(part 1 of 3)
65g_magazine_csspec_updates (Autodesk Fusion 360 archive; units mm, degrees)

design "65g_magazine_csspec_updates" references "65_g_floorplate"
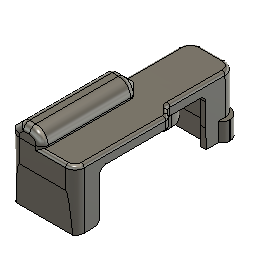
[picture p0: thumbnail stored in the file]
parameter "CartrigeOAL" = 57.9
parameter "magazineShoulder" = 35.6
parameter "feedLipRadius" = 5.6
parameter "primaryWallThickness" = 2
parameter "feedliplength" = 29.6
parameter "frontWidth" = 16
parameter "rearwidth" = 22
parameter "addtlfeedlipthickness" = 3.5
parameter "bananaFactor" = 1509
parameter "floorplateclearance" = 2
parameter "followerOffset" = -0.75
parameter "d1137" = 350
parameter "d372" = 1
parameter "d374" = 0.7
parameter "d376" = 0.7
parameter "d377" = -1
parameter "d378" = 0
parameter "d380" = 0.5
parameter "d387" = 7
parameter "d389" = 1
parameter "d390" = 4
parameter "d391" = 0.75
parameter "d392" = -9
parameter "d393" = 0
parameter "d394" = 10
parameter "d400" = 10
parameter "d401" = 5
parameter "d402" = -0.5
parameter "d403" = 0
parameter "d404" = 0
parameter "d405" = 0
parameter "d406" = 4
parameter "d407" = 3
parameter "d412" = 17
parameter "d413" = 1.5
parameter "d415" = 3
parameter "d418" = 6
parameter "d419" = 1.5
base_feature "Base Feature1" bodies "follower", "mag body", "feed geometry", "random cube", "placeholder to establish center"
derived_base_feature "Derived Base Feature2" bodies "main body", "updated lock lug", "template lock lug from m76"
remove_body "RemoveBody1"
sketch "top down profile" plane through (0, 0, 0) normal (0, 1, 0) x axis (1, 0, 0)
  line L1 (-11, 0) -> (0, 0)
  line L2 (0, 57.9) -> (0, 0)
  line L3 (-11, 35.6) -> (-11, 0)
  line L4 (-8, 44.9274) -> (-8, 53.9)
  line L5 (-4, 57.9) -> (0, 57.9)
  line L6 (-4, 57.9) -> (0, 57.9)
  line L7 (0, 57.9) -> (0, 0)
  line L8 (11, 35.6) -> (11, 0)
  line L9 (8, 44.9274) -> (8, 53.9)
  line L10 (4, 57.9) -> (0, 57.9)
  line L11 (11, 0) -> (0, 0)
  line L12 (-13, -2) -> (0, -2)
  line L13 (-4.2574, 61.8) -> (0, 61.8)
  line L14 (-13, 37) -> (-13, -2)
  line L15 (-6.3787, 60.9213) -> (-10.1219, 57.1781)
  line L16 (6.3787, 60.9213) -> (10.1219, 57.1781)
  line L17 (13, 37) -> (13, -2)
  line L18 (13, -2) -> (0, -2)
  line L19 (4.2574, 61.8) -> (0, 61.8)
  line L20 (-11, 27.6) -> (-13, 27.6)
  line L21 (-11, -2) -> (-11, 0)
  line L22 (-9.4578, 32.9452) -> (-8.5625, 43.1785)
  line L23 (0.2269, 43.1785) -> (-8.5625, 43.1785)
  line L24 (-9.9889, 31.486) -> (-11, 30.042)
  line L25 (-11.7322, 43.1785) -> (-8.5625, 43.1785)
  line L26 (-11, 49.3) -> (-8, 49.3)
  line L27 (-30.8129, 55.0827) -> (-11, 55)
  line L28 (-30.9385, 25) -> (-30.8129, 55.0827)
  line L29 (-13, 25) -> (-30.9385, 25)
  line L30 (-11, 45.4853) -> (-11, 55)
  line L31 (11, 45.4853) -> (11, 55)
  line L32 (-6, -4) -> (6, -4)
  line L33 (6, -2) -> (6, -4)
  line L34 (-6, -2) -> (-6, -4)
  arc A1 centre (-4, 53.9) radius 4 clockwise from (-8, 53.9) to (-4, 57.9)
  arc A2 centre (2, 35.6) radius 13 clockwise from (-11, 35.6) to (-8.5625, 43.1785)
  arc A3 centre (-11, 44.9274) radius 3 clockwise from (-8, 44.9274) to (-8.5625, 43.1785)
  arc A4 centre (-2, 35.6) radius 13 clockwise from (8.5625, 43.1785) to (11, 35.6)
  arc A5 centre (11, 44.9274) radius 3 clockwise from (8.5625, 43.1785) to (8, 44.9274)
  arc A6 centre (4, 53.9) radius 4 clockwise from (4, 57.9) to (8, 53.9)
  arc A7 centre (2, 37) radius 15 clockwise from (-13, 37) to (-11.4211, 43.6989)
  arc A8 centre (-15, 45.4853) radius 4 clockwise from (-11, 45.4853) to (-11.4211, 43.6989)
  arc A9 centre (-8.0005, 55.0568) radius 3 clockwise from (-11, 55) to (-10.1219, 57.1781)
  arc A10 centre (-4.2574, 58.8) radius 3 clockwise from (-6.3787, 60.9213) to (-4.2574, 61.8)
  arc A11 centre (4.2574, 58.8) radius 3 clockwise from (4.2574, 61.8) to (6.3787, 60.9213)
  arc A12 centre (8.0005, 55.0568) radius 3 clockwise from (10.1219, 57.1781) to (11, 55)
  arc A13 centre (15, 45.4853) radius 4 clockwise from (11.4211, 43.6989) to (11, 45.4853)
  arc A14 centre (-2, 37) radius 15 clockwise from (11.4211, 43.6989) to (13, 37)
  arc A15 centre (-12.4464, 33.2067) radius 3 clockwise from (-9.4578, 32.9452) to (-9.9889, 31.486)
  circle C1 centre (-10.808, 41.9164) radius 1.2808
  point P1 (0, 0)
  point P2 (0, 0)
  point P4 (0, 0)
  point P25 (0, 0)
  point P3 (-11, 0)
  point P16 (11, 0)
  point P14 (0, 0)
  point P5 (0, 57.9)
  point P15 (0, 57.9)
  point P7 (-4, 57.9)
  point P24 (4, 57.9)
  point P8 (-8, 53.9)
  point P22 (8, 53.9)
  point P10 (-11, 35.6)
  point P17 (11, 35.6)
  point P12 (-8, 44.9274)
  point P21 (8, 44.9274)
  point P13 (-8.5625, 43.1785)
  point P19 (8.5625, 43.1785)
  point P33 (-5.5, 61.8)
  point P26 (0, -2)
  point P52 (0, -2)
  point P27 (-13, -2)
  point P51 (13, -2)
  point P28 (-13, 37)
  point P50 (13, 37)
  point P30 (-11, 45.4853)
  point P46 (11, 45.4853)
  point P31 (-11.4211, 43.6989)
  point P48 (11.4211, 43.6989)
  point P34 (-10.1219, 57.1781)
  point P43 (10.1219, 57.1781)
  point P35 (-11, 55)
  point P45 (11, 55)
  point P37 (-6.3787, 60.9213)
  point P42 (6.3787, 60.9213)
  point P38 (-4.2574, 61.8)
  point P41 (4.2574, 61.8)
  point P54 (-13, 27.6)
  point P55 (-11, 27.6)
  point P56 (-11, -2)
  point P58 (-11, 30.042)
  point P62 (-11.7322, 43.1785)
  point P63 (-8, 49.3)
  point P67 (-13, 25)
  point P70 (6, -2)
  point P71 (-6, -2)
  point P68 (6, -4)
  point P69 (-6, -4)
  point P72 (-10.808, 41.9164)
  coincident P1 P2
  horizontal L1
  coincident P1 P4
  perpendicular L1 L2
  perpendicular L1 L3
  perpendicular L1 L4
  perpendicular L2 L5
  tangent L5 A1
  tangent L4 A1
  tangent L6 A1
  tangent L3 A2
  tangent A2 A3
  tangent L4 A3
  symmetric P2 L2 P25
  symmetric P3 L2 P16
  symmetric P4 L2 P14
  symmetric P5 L2 P15
  symmetric L2 P7 P24
  symmetric L2 A1 A6
  symmetric L2 P8 P22
  symmetric L2 P10 P17
  symmetric L2 A2 A4
  symmetric L2 P12 P21
  symmetric L2 P13 P19
  symmetric L2 A3 A5
  horizontal L12
  horizontal L13
  perpendicular L12 L14
  tangent L14 A7
  tangent A7 A8
  tangent L15 A9
  coincident P33 L15
  coincident L13 P33
  tangent L15 A10
  tangent L13 A10
  equal A9 A10
  symmetric L2 P26 P52
  symmetric L2 P27 P51
  symmetric L2 P28 P50
  symmetric L2 A7 A14
  symmetric L2 P30 P46
  symmetric L2 P31 P48
  symmetric L2 A8 A13
  symmetric L2 P34 P43
  symmetric L2 P35 P45
  symmetric L2 A9 A12
  symmetric L2 P37 P42
  symmetric L2 P38 P41
  symmetric L2 A10 A11
  coincident L14 P54
  coincident L3 P55
  perpendicular L3 L20
  coincident L12 P56
  perpendicular L12 L21
  horizontal L23
  coincident L3 P58
  tangent L22 A15
  tangent L24 A15
  horizontal L25
  coincident A8 P62
  coincident L4 P63
  perpendicular L27 L28
  coincident L14 P67
  perpendicular L14 L29
  tangent A8 L30
  vertical L30
  parallel L11 L32
  coincident L18 P70
  perpendicular L18 L33
  coincident L12 P71
  perpendicular L12 L34
  tangent A2 C1
  tangent A7 C1
  dimension "d571" distance P2 P3 = 11 (= "rearwidth / 2")
  dimension "d572" distance P4 P5 = 57.9 (= "CartrigeOAL")
  dimension "d573" distance P5 L4 = 8 (= "frontWidth / 2")
  dimension "d574" diameter A1 = 8
  dimension "d577" diameter A3 = 6
  dimension "d578" distance P26 P27 = 13 (= "d571 + 2 mm")
  dimension "d579" distance L1 L12 = 2 (= "primaryWallThickness")
  dimension "d580" distance L12 L13 = 63.8 (= "d572 + 5.9 mm")
  dimension "d586" radius A8 = 4
  dimension "d590" radius A9 = 3
  dimension "d591" angle L13 L15 = 135
  dimension "d601" distance L12 L20 = 29.6 (= "feedliplength")
  dimension "d618" angle L22 L23 = 95
  dimension "d622" radius A15 = 3
  dimension "d623" angle L3 L24 = 145
  dimension "d679" distance L13 L26 = 12.5
  dimension "d681" distance L13 P35 = 6.8
  dimension "d683" distance L3 L14 = 2 (= "d579")
  dimension "d685" distance P3 P10 = 35.6 (= "magazineShoulder")
  dimension "d686" distance L1 P28 = 37 (= "d685 + 1.4 mm")
  dimension "d699" distance P58 L25 = 13.1365
  dimension "d700" distance L7 L30 = 11 (= "d573 + 3 mm")
  dimension "d754" distance P68 P69 = 12
  dimension "d755" distance L7 P68 = 6 (= "d754 / 2")
  dimension "d756" distance L18 L32 = 2
  dimension "d779" diameter C1 = 2.5616
  dimension "d780" distance P30 P72 = 3.5688
sketch "Sketch4" plane through (0, 0, 0) normal (0, 1, 0) x axis (1, 0, 0)
  line L1 (2.35, 53.733) -> (2.35, 46.32)
  line L2 (2.35, 53.733) -> (2.35, 52.4025)
  line L3 (2.35, 48.3729) -> (2.35, 52.4025)
  line L4 (2.35, 45) -> (2.35, 48.3729)
  line L5 (2.35, 46.32) -> (2.35, 45)
  curve K1 (1.7875, 44.5687) -> (-0.65, 36.9798)
  line L6 (1.7875, 44.5687) -> (1.7875, 43.2511)
  line L7 (-0.65, 36.9798) -> (-0.65, 35.6726)
  line L8 (-0.65, 36.9798) -> (-0.65, 1.2627)
  line L9 (-0.65, 36.9798) -> (-0.65, 35.6726)
  line L10 (-0.65, 29.2298) -> (-0.65, 35.6726)
  line L11 (-0.65, 0.0025) -> (-0.65, 29.2298)
  line L12 (-0.65, 0.0025) -> (-0.65, 1.2627)
  curve K2 (2.35, 46.32) -> (1.7875, 44.5687)
  line L13 (2.35, 46.32) -> (2.35, 45)
  line L14 (1.7875, 44.5687) -> (1.7875, 43.2511)
  line L15 (0.8031, 31.5304) -> (1.7875, 43.2511)
  line L16 (-0.65, 29.2298) -> (0.3422, 30.4123)
  arc A1 centre (-1.1899, 31.6978) radius 2 clockwise from (0.8031, 31.5304) to (0.3422, 30.4123)
sketch "Banana Factor" plane through (0, 0, 0) normal (1, 0, 0) x axis (0, 1, 0)
  line L1 (0, -57.9) -> (0, 0)
  line L2 (0, -35.6) -> (0, 0)
  line L3 (0, -35.6) -> (0, -43.1785)
  line L4 (0, -43.1785) -> (0, -44.9274)
  line L5 (0, -44.9274) -> (0, -53.9)
  line L6 (0, -53.9) -> (0, -57.9)
  line L7 (0, -57.9) -> (0, 0)
  line L8 (0, -35.6) -> (0, 0)
  line L9 (0, -35.6) -> (0, -43.1785)
  line L10 (0, -43.1785) -> (0, -44.9274)
  line L11 (0, -44.9274) -> (0, -53.9)
  line L12 (0, -53.9) -> (0, -57.9)
  line L13 (0, -29.227) -> (0, 0)
  line L14 (0, -1538.227) -> (0, -29.227)
  circle C1 centre (0, -1538.227) radius 1509
  point P12 (0, 0)
  point P22 (0, 0)
  point P24 (0, -1538.227)
  point P25 (0, -1538.227)
  point P23 (0, -29.227)
  coincident P12 P22
  parallel L2 L13
  parallel L5 L14
  coincident P24 P25
  coincident P23 C1
  dimension "d593" distance P22 P23 = 29.227
  dimension "d594" distance P23 P24 = 1509 (= "bananaFactor")
sweep "Sweep1" sketch "top down profile" TwistAngle 0 TaperAngle 0
sketch "feed lip curvature/radius" plane through (0, 0, 0) normal (0, 0, 1) x axis (1, 0, 0)
  line L1 (-5.4, 0) -> (-11, 0)
  line L2 (-5.4, 5.6) -> (-5.4, 0)
  curve K1 (0.2, 3.5) -> (-11, 3.5)
  curve K2 (-5.4, 5.5588) -> (-5.4, 1.4412)
  curve K3 (-5.4, 6.6) -> (-5.4, -6.6)
  curve K4 (-11, 0) -> (0.2, 0)
  line L3 (0.7, 0) -> (-5.4, 0)
  circle C1 centre (-5.4, 0) radius 5.6
  closed curve K5 centre (-5.4, 3.5)
  closed curve K6 centre (-5.4, 0)
  point P2 (-11, 0)
  point P3 (-11, 0)
  point P4 (-5.4, 0)
  point P5 (-5.4, 0)
  point P6 (-5.4, 5.6)
  point P8 (-11, 3.5)
  point P9 (0.2, 3.5)
  point P10 (-5.4, 1.4412)
  point P11 (-5.4, 5.5588)
  point P13 (-5.4, -6.6)
  point P14 (-5.4, 6.6)
  point P15 (0.2, 0)
  point P16 (-11, 0)
  point P7 (-5.4, 3.5)
  coincident P2 P3
  horizontal L1
  coincident P4 P5
  coincident P2 C1
  coincident C1 P6
  perpendicular L1 L2
  coincident K5 P8
  coincident K5 P9
  coincident K5 P10
  coincident K5 P11
  horizontal K1
  collinear L2 K2
  coincident L2 P11
  coincident K6 P13
  coincident K6 P14
  coincident K6 P15
  coincident K6 P16
  concentric C1 K6
  coincident P3 P16
  horizontal L3
  dimension "d602" distance P3 P4 = 5.6 (= "feedLipRadius")
  dimension "d730" distance K5 = 11.2 (= "feedLipRadius * 2")
  dimension "d731" distance P5 K1 = 3.5 (= "addtlfeedlipthickness")
  dimension "d746" = 4.1176 (= "d747 * 2 / 1.02")
  dimension "d747" distance P6 P7 = 2.1
  dimension "d1105" distance K6 = 13.2
sweep "Sweep2" sketch "top down profile" TwistAngle 0 TaperAngle 0 bodies "feed lip"
extrude "Extrude2" new body sketch "top down profile" profile of L3 L12 L14 L20 L21 along normal blind 3.5 (= "addtlfeedlipthickness")
sweep "Sweep1" TwistAngle 0 TaperAngle -0.8
extrude "Extrude9" new body sketch "top down profile" profile of L3 L12 L14 L20 L21 along normal blind 3.5 (= "addtlfeedlipthickness")
sweep "Sweep5" TwistAngle 0 TaperAngle 0
move "Move1"
extrude "Extrude17" cut sketch "feed lip curvature/radius" profile of C1 K5 K6 to an object Side2Offset 0
sketch "feed lip fill in" plane through (0, 0, 2) normal (0, 0, 1) x axis (1, 0, 0)
  line L1 (-11, 0) -> (-13, 0)
  line L2 (-6.3525, 7.5401) -> (-6.2247, 6.528)
  line L3 (-6.2247, 0) -> (-6.2247, 6.528)
  line L4 (-13, 0) -> (0, 0)
  line L5 (-13, 0) -> (-13, 3.5)
  line L6 (-6.575, 7.5184) -> (-6.5744, 7.5087)
  curve K1 (-6.575, 7.5184) -> (-13, 3.5)
  line L7 (-6.5751, 12.5087) -> (-6.5744, 7.5087)
  line L8 (-18, 0) -> (-13, 0)
  line L9 (-18, 12.7693) -> (-18, 0)
  line L10 (-6.5751, 12.5087) -> (-18, 12.7693)
  arc A1 centre (-5.4, 0) radius 7.6 clockwise from (-6.5744, 7.5087) to (-6.3525, 7.5401)
  closed curve K2 centre (-5.4, 0)
  point P4 (-6.2247, 6.528)
  point P7 (-6.2247, 6.528)
  point P8 (-6.2247, 0)
  point P2 (-6.5744, 7.5087)
  point P14 (-6.5744, 7.5087)
  point P11 (-13, 0)
  point P16 (-13, 0)
  point P15 (-6.5751, 12.5087)
  point P17 (-18, 0)
  coincident P4 P7
  coincident P8 L4
  perpendicular L3 L4
  coincident P2 P14
  coincident P11 P16
  perpendicular L5 L8
  perpendicular L8 L9
  dimension "d1089" distance P14 P15 = 5
  dimension "d1090" distance P16 P17 = 5
extrude "Extrude1" add sketch "feed lip fill in" profile of L4 L3 against normal blind 2
sketch "Draft pull tool" plane through (0, 0, 0) normal (0, 0, 1) x axis (1, 0, 0)
  line L1 (-6.2247, 6.528) -> (-6.3525, 7.5401)
  line L2 (-14.3525, 7.5401) -> (-6.3525, 7.5401)
  line L3 (-14.3525, 6.5401) -> (-14.3525, 7.5401)
  line L4 (-6.3525, 6.5401) -> (-14.3525, 6.5401)
  line L5 (-6.3525, 7.5401) -> (-6.3525, 6.5401)
  arc A1 centre (-5.4, 0) radius 7.6 clockwise from (-6.5744, 7.5087) to (-6.3525, 7.5401)
  point P2 (-6.3525, 7.5401)
  point P6 (-6.3525, 7.5401)
  point P7 (-14.3525, 7.5401)
  point P9 (-6.3525, 6.5401)
  horizontal L2
  vertical L3
  horizontal L4
  vertical L5
  coincident P2 P6
  dimension "d612" distance P6 P7 = 8
  dimension "d613" distance P6 P9 = 1
extrude "Extrude2" new body sketch "Draft pull tool" against normal blind 25 bodies "draft tool"
extrude "Extrude3" new body sketch "top down profile" profile of L3 L4 A2 A3 L14 A7 A8 L20 L22 L24 A15 L25 L26 along normal blind 3
draft "Draft2" Angle1 -45 Angle2 0
combine "Combine1"
sweep "Sweep3" sketch "top down profile" TwistAngle 0 TaperAngle 0
sweep "Sweep4" sketch "top down profile" TwistAngle 0 TaperAngle 0
sketch "cut draft angle between feed lips" plane through (0, 0, 0) normal (1, 0, 0) x axis (0, 1, 0)
  line L1 (3.8726, -39.715) -> (0, -49.3)
  line L2 (7, -39.715) -> (3.8726, -39.715)
  line L3 (7, -69.3) -> (7, -39.715)
  line L4 (0, -69.3) -> (7, -69.3)
  line L5 (0, -49.3) -> (0, -69.3)
  line L6 (0, 2) -> (0, -37)
  line L7 (-163.9995, -45.9848) -> (-168.26, -7.2183)
  line L8 (0, -57.9) -> (0, 0)
  arc A1 centre (0, -1538.227) radius 1540.227 clockwise from (-168.26, -7.2183) to (0, 2)
  arc A2 centre (0, -1538.227) radius 1501.227 clockwise from (-163.9995, -45.9848) to (0, -37)
  point P4 (7, -69.3)
  point P5 (0, -69.3)
  point P2 (3.8726, -39.715)
  point P13 (0, -49.3)
  point P3 (7, -39.715)
  point P6 (0, -49.3)
  point P12 (0, 2)
  perpendicular L2 L3
  perpendicular L3 L4
  vertical L3
  vertical L5
  dimension "d691" distance P4 P5 = 7
  dimension "d694" distance P2 P13 = 10.3377
  dimension "d695" angle L1 L8 = 158
  dimension "d696" distance P2 P3 = 3.1274
  dimension "d697" distance P6 P12 = 51.3 (= "magazineShoulder + primaryWallThickness + 13.7 mm")
  dimension "d698" distance P5 P6 = 20
extrude "Extrude1" cut sketch "cut draft angle between feed lips" profile of L1 L2 L3 L4 L5 against normal blind 13.5
combine "Combine2"
fillet "Fillet2" radius 1
mirror "Mirror1" mirrorStitchTolerance 0.1 bodies "feed lip (1)"
sketch "Sketch6" plane through (0, 0, 0) normal (0, 0, 1) x axis (1, 0, 0)
sketch "cut front clearance for rounds" plane through (0, 0, 0) normal (0, 0, 1) x axis (1, 0, 0)
  line L1 (-8, -3.1) -> (-8, 0)
  line L2 (8, -3.1) -> (8, 0)
  line L3 (-8, -3.1) -> (8, -3.1)
  line L4 (8, 0) -> (-8, 0)
  circle C1 centre (4.9, 0) radius 3.1
  circle C2 centre (-4.9, 0) radius 3.1
  point P3 (-8, 0)
  point P4 (-8, 0)
  point P2 (8, 0)
  point P6 (8, 0)
  point P5 (-8, -3.1)
  point P7 (8, -3.1)
  coincident P3 P4
  vertical L1
  coincident P2 P6
  vertical L2
  tangent L2 C1
  tangent L3 C1
  tangent L1 C2
  tangent L3 C2
  dimension "d656" distance P4 P5 = 3.1
  dimension "d657" distance P6 P7 = 3.1
  dimension "d659" diameter C1 = 6.2 (= "d657 * 2")
  dimension "d660" diameter C2 = 6.2 (= "d659")
move "Move3"
sketch "Sketch7" plane through (0, 0, 0) normal (0, 0, 1) x axis (1, 0, 0)
sketch "locking lug profile" plane through (0, 0, 0) normal (1, 0, 0) x axis (0, 1, 0)
  line L1 (-20.5632, -63.0982) -> (-16.5, -59.6888)
  line L2 (-10.0812, -59.6888) -> (-16.5, -59.6888)
  line L3 (1.3778, -59.6) -> (-3.1, -59.6)
  line L4 (-6.0779, -62.5779) -> (-3.1, -59.6)
  line L5 (2.907, -59.6) -> (-3.1, -59.6)
  line L6 (-7.9604, -62.5779) -> (-9.5957, -59.6279)
  line L7 (-3.8651, -59.6279) -> (-9.5957, -59.6279)
  line L8 (-6.0779, -62.5779) -> (-7.9604, -62.5779)
  line L9 (-20.5632, -69) -> (-20.5632, -63.0982)
  line L10 (1.3778, -69) -> (-20.5632, -69)
  line L11 (1.3778, -69) -> (1.3778, -59.6)
  line L12 (0, -55) -> (0, -57.1781)
  line L13 (0, -60.9213) -> (0, -57.1781)
  line L14 (0, -60.9213) -> (0, -61.8)
  line L15 (-10.0805, -58.7533) -> (-9.5957, -59.6279)
  line L16 (-2.2533, -58.7533) -> (-3.1, -59.6)
  line L17 (-10.0805, -58.7533) -> (-2.2533, -58.7533)
  line L18 (0, 2) -> (0, -37)
  line L19 (-163.9995, -45.9848) -> (-168.26, -7.2183)
  line L20 (1.3778, -51) -> (1.3778, -59.6)
  arc A1 centre (0.0013, -1538.227) radius 1478.6303 clockwise from (-16.5, -59.6888) to (-3.1, -59.6)
  arc A2 centre (0, -1538.227) radius 1540.227 clockwise from (-168.26, -7.2183) to (0, 2)
  arc A3 centre (0, -1538.227) radius 1501.227 clockwise from (-163.9995, -45.9848) to (0, -37)
  point P9 (-9.5957, -59.6279)
  point P19 (-3.1, -59.6)
  point P23 (0, 2)
  point P21 (-2.2533, -58.7533)
  point P20 (-10.0805, -58.7533)
  point P13 (-20.5632, -69)
  point P14 (1.3778, -69)
  point P4 (-16.5, -59.6888)
  point P5 (-20.5632, -63.0982)
  horizontal L2
  horizontal L3
  horizontal L5
  horizontal L7
  coincident A1 P9
  vertical L9
  perpendicular L9 L10
  perpendicular L10 L11
  coincident A1 P19
  parallel L6 L15
  collinear L4 L16
  horizontal L17
  perpendicular L3 L20
  dimension "d665" angle L1 L2 = 140
  dimension "d666" angle L4 L5 = 135
  dimension "d667" angle L6 L7 = 61
  dimension "d701" distance L3 P23 = 61.6 (= "CartrigeOAL + 3.7 mm")
  dimension "d702" distance L5 L17 = 0.8467
  dimension "d704" distance P21 L20 = 3.6311
  dimension "d705" distance P20 P21 = 7.8272
  dimension "d706" distance P13 P14 = 21.941
  dimension "d707" distance P4 P5 = 5.3041
extrude "Extrude6" cut sketch "locking lug profile" profile of A1 L1 L3 L4 L6 L8 L9 L10 L11 distance 11
extrude "Extrude7" new body sketch "locking lug profile" profile of A1 L4 L6 L8 L15 L17 distance 5.2
draft "Draft3" Angle1 30 Angle2 0
extrude "Extrude8" cut sketch "cut front clearance for rounds" profile of L3 C1 C2 L4 against normal blind 69.48 (magnitude of "CartrigeOAL * -1.2")
combine "Combine3" bodies "feed lip (1)", "feed lip"
fillet "Fillet12" radius 1
fillet "Fillet6" radius 2
fillet "Fillet7" radius 2.75
fillet "Fillet8" radius 1
fillet "Fillet9" radius 1
sketch "Rear locking lug profile" plane through (0, 0, 0) normal (1, 0, 0) x axis (0, 1, 0)
  line L1 (0, -37) -> (0, 2)
  line L2 (-18.7, 4.4) -> (0, 2)
  line L3 (-29.7, 4.7) -> (-18.7, 4.4)
  line L4 (-44.05, 1.37) -> (-29.7, 4.7)
  line L5 (0, 23) -> (0, 2)
  line L6 (-21.7, 0.8) -> (-21.7, 4.4818)
  line L7 (-26.4, 0.8) -> (-21.7, 0.8)
  line L8 (-26.4, 4.61) -> (-26.4, 0.8)
  line L9 (-21.7, 10.2818) -> (-21.7, 4.4818)
  line L10 (-24.5, 9.9009) -> (-21.7, 10.2818)
  line L11 (-26.4, 4.61) -> (-24.5, 9.9009)
  line L12 (7.5184, 2) -> (3.5, 2)
  line L13 (6.0649, 3.7246) -> (-18.7, 4.4)
  line L14 (7.5235, 2.1843) -> (7.5184, 2)
  line L15 (0, 2) -> (7.5184, 2)
  arc A1 centre (0, -1538.227) radius 1540.227 clockwise from (-168.26, -7.2183) to (0, 2)
  arc A2 centre (6.024, 2.2252) radius 1.5 clockwise from (6.0649, 3.7246) to (7.5235, 2.1843)
  point P2 (0, 2)
  point P4 (0, 2)
  point P7 (-44.05, 1.37)
  point P8 (0, 2)
  point P11 (0, 2)
  point P13 (-21.7, 4.4818)
  point P16 (-26.4, 4.61)
  point P20 (7.5184, 2)
  point P21 (7.5184, 2)
  point P5 (-18.7, 4.4)
  point P6 (-29.7, 4.7)
  point P14 (-21.7, 0.8)
  point P15 (-26.4, 0.8)
  point P17 (-21.7, 10.2818)
  point P18 (-24.5, 9.9009)
  coincident P2 P4
  coincident P7 A1
  coincident P8 P11
  vertical L5
  coincident L3 P13
  vertical L6
  perpendicular L6 L7
  coincident L3 P16
  perpendicular L7 L8
  parallel L6 L9
  parallel L3 L13
  coincident P20 P21
  perpendicular L13 L14
  tangent L14 A2
  tangent L13 A2
  dimension "d766" distance P4 P5 = 18.7
  dimension "d767" distance P4 P6 = 29.7
  dimension "d768" distance P7 P11 = 44.05
  dimension "d769" distance P5 P11 = 2.4
  dimension "d770" distance P6 P11 = 2.7
  dimension "d771" distance P11 P14 = 1.2
  dimension "d772" distance P11 P13 = 21.7
  dimension "d773" distance P14 P15 = 4.7
  dimension "d1081" distance P13 P17 = 5.8
  dimension "d1088" radius A2 = 1.5
  dimension "d1100" angle L10 L11 = 117.5
  dimension "d1101" distance P17 P18 = 2.8
sketch "recut back profile after reinforcement" plane through (0, 0, 2) normal (0, 0, 1) x axis (1, 0, 0)
  line L1 (6.2247, 6.528) -> (6.2731, 6.911)
  line L2 (6.2247, 2.75) -> (6.2247, 6.528)
  line L3 (13, 0) -> (3.4747, 0)
  line L4 (13, 3.5) -> (13, 0)
  curve K1 (6.575, 7.5184) -> (13, 3.5)
  line L5 (6.5744, 7.5087) -> (6.575, 7.5184)
  line L6 (-6.575, 7.5184) -> (-6.5744, 7.5087)
  curve K2 (-6.575, 7.5184) -> (-13, 3.5)
  line L7 (-13, 0) -> (-13, 3.5)
  line L8 (-3.4747, 0) -> (-13, 0)
  line L9 (-6.2247, 6.528) -> (-6.2247, 2.75)
  line L10 (-6.2731, 6.911) -> (-6.2247, 6.528)
  line L11 (3.4747, 0) -> (-3.4747, 0)
  line L12 (16, 0) -> (13, 0)
  line L13 (16, 15) -> (16, 0)
  line L14 (-16, 0) -> (-13, 0)
  line L15 (-16, 15) -> (-16, 0)
  line L16 (16, 15) -> (-16, 15)
  arc A1 centre (7.2652, 6.7857) radius 1 clockwise from (6.2731, 6.911) to (6.5744, 7.5087)
  arc A2 centre (3.4747, 2.75) radius 2.75 clockwise from (6.2247, 2.75) to (3.4747, 0)
  arc A3 centre (-7.2652, 6.7857) radius 1 clockwise from (-6.5744, 7.5087) to (-6.2731, 6.911)
  arc A4 centre (-3.4747, 2.75) radius 2.75 clockwise from (-3.4747, 0) to (-6.2247, 2.75)
  point P18 (-3.4747, 0)
  point P22 (-3.4747, 0)
  point P7 (3.4747, 0)
  point P23 (3.4747, 0)
  point P9 (13, 0)
  point P24 (13, 0)
  point P17 (-13, 0)
  point P27 (-13, 0)
  point P25 (16, 0)
  point P26 (16, 15)
  point P28 (-16, 0)
  point P29 (-16, 15)
  coincident P18 P22
  coincident P7 P23
  coincident P9 P24
  perpendicular L4 L12
  perpendicular L12 L13
  coincident P17 P27
  perpendicular L7 L14
  perpendicular L14 L15
  dimension "d1093" distance P24 P25 = 3
  dimension "d1094" distance P25 P26 = 15
  dimension "d1095" distance P27 P28 = 3
  dimension "d1096" distance P28 P29 = 15
extrude "Extrude10" add sketch "Rear locking lug profile" profile of L2 L3 L4 A1 L6 L8 L12 L13 L14 A2 L15 distance 13
extrude "Extrude16" cut sketch "recut back profile after reinforcement" profile of A1 L1 L2 A2 L4 K1 L5 A3 L6 K2 L7 A4 L9 L10 L11 L12 L13 L14 L15 L16 along normal blind 6
sweep "Sweep6" sketch "top down profile" TwistAngle 0 TaperAngle 0
chamfer "Chamfer1" distance 15 distance 2
combine "Combine4"
extrude "Extrude3" cut sketch "Rear locking lug profile" profile of L3 A1 L6 L7 L8 distance 5.8
extrude "Extrude15" new body sketch "Rear locking lug profile" profile of L3 A1 L6 L7 L8 L9 L10 L11 distance 5.7 bodies "updated locking lug"
offset_faces "OffsetFaces1" distance -0.07
offset_faces "OffsetFaces2" distance -0.07
fillet "Fillet13" radius 1.5
fillet "Fillet15" radius 1
fillet "Fillet10" radius 1 7.5
fillet "Fillet11" radius 1
move "Move4"
move "Move5"
sketch "CutBasePlateClearance" plane through (0, -167.0358, -18.3575) normal (0, -0.994, -0.1092) x axis (-1, 0, 0)
  line L1 (-10, -9.2063) -> (10, -9.2063)
  line L2 (-11, 26.3937) -> (-11, -8.2063)
  line L3 (-8, 44.6937) -> (-8, 35.7211)
  line L4 (4, 48.6937) -> (-4, 48.6937)
  line L5 (8, 35.7211) -> (8, 44.6937)
  line L6 (11, -8.2063) -> (11, 26.3937)
  line L7 (13, 27.7937) -> (13, -9.7063)
  line L8 (6.3787, 51.715) -> (10.1219, 47.9719)
  line L9 (-4.2574, 52.5937) -> (4.2574, 52.5937)
  line L10 (-10.1219, 47.9719) -> (-6.3787, 51.715)
  line L11 (-13, -9.7063) -> (-13, 27.7937)
  line L12 (11.5, -11.2063) -> (7, -11.2063)
  line L13 (5, -13.2063) -> (-5, -13.2063)
  line L14 (0, 52.5937) -> (0, -13.2063)
  line L15 (-12.3, 52.5937) -> (-12.3, -13.2063)
  line L16 (12.3, 52.5937) -> (12.3, -13.2063)
  line L17 (-30, -13.2063) -> (30, -13.2063)
  line L18 (-30, 52.5937) -> (30, 52.5937)
  line L19 (-15.3, 52.5937) -> (-15.3, -13.2063)
  line L20 (15.3, 52.5937) -> (15.3, -13.2063)
  line L21 (11, 45.7937) -> (11, 36.279)
  line L22 (-11, 36.279) -> (-11, 45.7937)
  line L23 (-7, -11.2063) -> (-11.5, -11.2063)
  arc A1 centre (-10, -8.2063) radius 1 clockwise from (-10, -9.2063) to (-11, -8.2063)
  arc A2 centre (2, 26.3937) radius 13 clockwise from (-11, 26.3937) to (-8.5625, 33.9722)
  arc A3 centre (-11, 35.7211) radius 3 clockwise from (-8, 35.7211) to (-8.5625, 33.9722)
  arc A4 centre (-4, 44.6937) radius 4 clockwise from (-8, 44.6937) to (-4, 48.6937)
  arc A5 centre (4, 44.6937) radius 4 clockwise from (4, 48.6937) to (8, 44.6937)
  arc A6 centre (11, 35.7211) radius 3 clockwise from (8.5625, 33.9722) to (8, 35.7211)
  arc A7 centre (-2, 26.3937) radius 13 clockwise from (8.5625, 33.9722) to (11, 26.3937)
  arc A8 centre (10, -8.2063) radius 1 clockwise from (11, -8.2063) to (10, -9.2063)
  arc A9 centre (4.2574, 49.5937) radius 3 clockwise from (4.2574, 52.5937) to (6.3787, 51.715)
  arc A10 centre (-4.2574, 49.5937) radius 3 clockwise from (-6.3787, 51.715) to (-4.2574, 52.5937)
  arc A11 centre (11.5, -9.7063) radius 1.5 clockwise from (13, -9.7063) to (11.5, -11.2063)
  arc A12 centre (-2, 27.7937) radius 15 clockwise from (11.4211, 34.4926) to (13, 27.7937)
  arc A13 centre (15, 36.279) radius 4 clockwise from (11.4211, 34.4926) to (11, 36.279)
  arc A14 centre (8.0005, 45.8505) radius 3 clockwise from (10.1219, 47.9719) to (11, 45.7937)
  arc A15 centre (-8.0005, 45.8505) radius 3 clockwise from (-11, 45.7937) to (-10.1219, 47.9719)
  arc A16 centre (-15, 36.279) radius 4 clockwise from (-11, 36.279) to (-11.4211, 34.4926)
  arc A17 centre (2, 27.7937) radius 15 clockwise from (-13, 27.7937) to (-11.4211, 34.4926)
  arc A18 centre (-11.5, -9.7063) radius 1.5 clockwise from (-11.5, -11.2063) to (-13, -9.7063)
  arc A19 centre (5, -12.2063) radius 1 clockwise from (6, -12.2063) to (5, -13.2063)
  arc A20 centre (7, -12.2063) radius 1 clockwise from (6, -12.2063) to (7, -11.2063)
  arc A21 centre (-7, -12.2063) radius 1 clockwise from (-7, -11.2063) to (-6, -12.2063)
  arc A22 centre (-5, -12.2063) radius 1 clockwise from (-5, -13.2063) to (-6, -12.2063)
  point P40 (0, -13.2063)
  point P41 (0, 52.5937)
  point P42 (-12.3, -13.2063)
  point P44 (12.3, -13.2063)
  point P45 (12.3, 52.5937)
  point P43 (-12.3, 52.5937)
  point P46 (30, -13.2063)
  point P47 (-30, -13.2063)
  midpoint L13 P40
  midpoint L9 P41
  vertical L15
  vertical L16
  horizontal L17
  coincident P40 L17
  coincident P42 L17
  coincident P44 L17
  dimension "d801" distance P40 P41 = 65.8
  dimension "d802" distance P44 P45 = 65.8 (= "d801")
  dimension "d803" distance P42 P43 = 65.8 (= "d801")
  dimension "d804" distance L15 L16 = 24.6
  dimension "d805" distance L14 L15 = 12.3 (= "d804 / 2")
  dimension "d806" distance P46 P47 = 60
  dimension "d807" distance P40 P47 = 30 (= "d806 / 2")
  dimension "d808" = 65.8
  dimension "d809" = -3
  dimension "d810" = 3
extrude "Extrude12" cut sketch "CutBasePlateClearance" profile of L7 L11 L15 L16 L17 L18 L19 L20 against normal blind 2 (magnitude of "-1 * ( floorplateclearance )")
draft "Draft4" Angle1 50 Angle2 0
draft "Draft5" Angle1 50 Angle2 0
sketch "Sketch8" plane through (0, -167.0358, -18.3575) normal (0, -0.994, -0.1092) x axis (-1, 0, 0)
sketch "addLipForBasePlate" plane through (0, -167.0358, -18.3575) normal (0, -0.994, -0.1092) x axis (-1, 0, 0)
  line L1 (6.2, -14.5063) -> (-6.2, -14.5063)
  line L2 (-14.2, -6.5063) -> (-14.2, 32.2937)
  line L3 (14.2, -6.5063) -> (14.2, 32.2937)
  line L4 (0, 52.5937) -> (0, -13.2063)
  line L5 (4.4118, 54.4937) -> (-4.4118, 54.4937)
  line L6 (-10, -9.2063) -> (10, -9.2063)
  line L7 (11.3055, 48.7093) -> (14.2, 32.2937)
  line L8 (-11.3055, 48.7093) -> (-14.2, 32.2937)
  line L9 (12.3, 32.3225) -> (12.3, -10.9751)
  line L10 (11, 45.7937) -> (11, 36.279)
  line L11 (6.3787, 51.715) -> (10.1219, 47.9719)
  line L12 (-4.2574, 52.5937) -> (4.2574, 52.5937)
  line L13 (-10.1219, 47.9719) -> (-6.3787, 51.715)
  line L14 (-11, 36.279) -> (-11, 45.7937)
  line L15 (-12.3, -10.9751) -> (-12.3, 32.3225)
  line L16 (-7, -11.2063) -> (-11.5, -11.2063)
  line L17 (5, -13.2063) -> (-5, -13.2063)
  line L18 (11.5, -11.2063) -> (7, -11.2063)
  line L19 (-10, -9.2063) -> (10, -9.2063)
  line L20 (-11, 26.3937) -> (-11, -8.2063)
  line L21 (-8, 44.6937) -> (-8, 35.7211)
  line L22 (4, 48.6937) -> (-4, 48.6937)
  line L23 (8, 35.7211) -> (8, 44.6937)
  line L24 (11, -8.2063) -> (11, 26.3937)
  arc A1 centre (4.4118, 47.4937) radius 7 clockwise from (4.4118, 54.4937) to (11.3055, 48.7093)
  arc A2 centre (-4.4118, 47.4937) radius 7 clockwise from (-11.3055, 48.7093) to (-4.4118, 54.4937)
  arc A3 centre (6.2, -6.5063) radius 8 clockwise from (14.2, -6.5063) to (6.2, -14.5063)
  arc A4 centre (-6.2, -6.5063) radius 8 clockwise from (-6.2, -14.5063) to (-14.2, -6.5063)
  arc A5 centre (-2, 27.7937) radius 15 clockwise from (11.4211, 34.4926) to (12.3, 32.3225)
  arc A6 centre (15, 36.279) radius 4 clockwise from (11.4211, 34.4926) to (11, 36.279)
  arc A7 centre (8.0005, 45.8505) radius 3 clockwise from (10.1219, 47.9719) to (11, 45.7937)
  arc A8 centre (4.2574, 49.5937) radius 3 clockwise from (4.2574, 52.5937) to (6.3787, 51.715)
  arc A9 centre (-4.2574, 49.5937) radius 3 clockwise from (-6.3787, 51.715) to (-4.2574, 52.5937)
  arc A10 centre (-8.0005, 45.8505) radius 3 clockwise from (-11, 45.7937) to (-10.1219, 47.9719)
  arc A11 centre (-15, 36.279) radius 4 clockwise from (-11, 36.279) to (-11.4211, 34.4926)
  arc A12 centre (2, 27.7937) radius 15 clockwise from (-12.3, 32.3225) to (-11.4211, 34.4926)
  arc A13 centre (-11.5, -9.7063) radius 1.5 clockwise from (-11.5, -11.2063) to (-12.3, -10.9751)
  arc A14 centre (-7, -12.2063) radius 1 clockwise from (-7, -11.2063) to (-6, -12.2063)
  arc A15 centre (-5, -12.2063) radius 1 clockwise from (-5, -13.2063) to (-6, -12.2063)
  arc A16 centre (5, -12.2063) radius 1 clockwise from (6, -12.2063) to (5, -13.2063)
  arc A17 centre (7, -12.2063) radius 1 clockwise from (6, -12.2063) to (7, -11.2063)
  arc A18 centre (11.5, -9.7063) radius 1.5 clockwise from (12.3, -10.9751) to (11.5, -11.2063)
  arc A19 centre (-10, -8.2063) radius 1 clockwise from (-10, -9.2063) to (-11, -8.2063)
  arc A20 centre (2, 26.3937) radius 13 clockwise from (-11, 26.3937) to (-8.5625, 33.9722)
  arc A21 centre (-11, 35.7211) radius 3 clockwise from (-8, 35.7211) to (-8.5625, 33.9722)
  arc A22 centre (-4, 44.6937) radius 4 clockwise from (-8, 44.6937) to (-4, 48.6937)
  arc A23 centre (4, 44.6937) radius 4 clockwise from (4, 48.6937) to (8, 44.6937)
  arc A24 centre (11, 35.7211) radius 3 clockwise from (8.5625, 33.9722) to (8, 35.7211)
  arc A25 centre (-2, 26.3937) radius 13 clockwise from (8.5625, 33.9722) to (11, 26.3937)
  arc A26 centre (10, -8.2063) radius 1 clockwise from (11, -8.2063) to (10, -9.2063)
  point P5 (14.2, 32.2937)
  point P10 (-14.2, 32.2937)
  point P3 (14.2, -14.5063)
  point P2 (-14.2, -14.5063)
  point P4 (-14.2, 32.2937)
  horizontal L1
  vertical L2
  vertical L3
  horizontal L5
  symmetric P5 L4 P10
  tangent L5 A1
  tangent L7 A1
  tangent L8 A2
  tangent L5 A2
  equal A1 A2
  coincident P3 L1
  tangent L3 A3
  tangent L1 A3
  coincident P2 L1
  tangent L2 A4
  tangent L1 A4
  equal A3 A4
  dimension "d818" distance L2 L3 = 28.4
  dimension "d819" distance L3 L4 = 14.2 (= "d818 / 2")
  dimension "d820" distance L1 L5 = 69
  dimension "d821" distance P2 P3 = 28.4 (= "d818")
  dimension "d822" distance P3 L4 = 14.2 (= "d821 / 2")
  dimension "d823" distance P2 P4 = 46.8
  dimension "d824" distance P3 P5 = 46.8 (= "d823")
  dimension "d825" distance L1 L6 = 5.3
  dimension "d826" angle L3 L7 = 170
  dimension "d827" radius A1 = 7
  dimension "d828" radius A3 = 8
  dimension "d831" distance L5 L12 = 1.9
  dimension "d832" distance L1 L17 = 1.3
extrude "Extrude13" add sketch "addLipForBasePlate" along normal blind 3
sketch "Sketch9" plane through (0, -1.6113, 14.6963) normal (0, -0.109, 0.994) x axis (1, 0, 0)
  curve K1 (2.0685, -171.2612) -> (-1.9315, -171.2612)
  line L1 (6.2685, -171.2612) -> (2.0685, -171.2612)
  line L2 (6.2685, -168.2612) -> (6.2685, -171.2612)
  line L3 (-6.1315, -168.2612) -> (6.2685, -168.2612)
  line L4 (-6.1315, -171.2612) -> (-6.1315, -168.2612)
  line L5 (-1.9315, -171.2612) -> (-6.1315, -171.2612)
  line L6 (3.0065, -170.5006) -> (-2.7534, -170.5006)
  curve K2 (2.0685, -171.2612) -> (-1.9315, -171.2612)
  horizontal L6
sketch "floor plate retainer cut" plane through (0, -1.5847, 14.4195) normal (0, -0.1092, 0.994) x axis (1, 0, 0)
  line L1 (-6.2, -168.0415) -> (6.2, -168.0415)
  line L2 (-6.2, -171.0415) -> (-6.2, -168.0415)
  line L3 (6.2, -171.0415) -> (-6.2, -171.0415)
  line L4 (6.2, -168.0415) -> (6.2, -171.0415)
  line L5 (3.7106, -170.2415) -> (-4, -170.2415)
  line L6 (0, -177.3169) -> (0, -171.0415)
  line L7 (-2, -171.0415) -> (2, -171.0415)
  arc A1 centre (0, -173.1415) radius 2.9 clockwise from (-2, -171.0415) to (2, -171.0415)
  point P9 (0, -171.0415)
  point P6 (0, -173.1415)
  point P11 (2, -171.0415)
  point P12 (-2, -171.0415)
  horizontal L5
  tangent L5 A1
  midpoint L3 P9
  perpendicular L3 L6
  coincident P6 L6
  coincident L3 P11
  coincident L3 P12
  dimension "d833" distance L3 L5 = 0.8
  dimension "d834" distance P11 P12 = 4
extrude "Extrude14" cut sketch "floor plate retainer cut" profile of L3 A1 against normal blind 8
external_derived "ExternalDerived1"
move "Move6"
sketch "matchingFloorPlate" plane through (0, 0, 0) normal (0, 1, 0) x axis (1, 0, 0)
  line L1 (-11, 35.6) -> (-11, 0)
  line L2 (0, 57.9) -> (0, 0)
  line L3 (-4, 57.9) -> (0, 57.9)
  line L4 (-8, 44.9274) -> (-8, 53.9)
  line L5 (0, 57.9) -> (0, 0)
  line L6 (11, 0) -> (0, 0)
  line L7 (11, 35.6) -> (11, 0)
  line L8 (8, 44.9274) -> (8, 53.9)
  line L9 (4, 57.9) -> (0, 57.9)
  line L10 (-11, 0) -> (0, 0)
  line L11 (-0.5, 57.4) -> (-0.5, 0.5)
  line L12 (-4, 57.4) -> (-0.5, 57.4)
  line L13 (-7.5, 44.9274) -> (-7.5, 53.9)
  line L14 (-10.5, 35.6) -> (-10.5, 5.5)
  line L15 (-5.5, 0.5) -> (-0.5, 0.5)
  line L16 (0.5, 57.4) -> (0.5, 0.5)
  line L17 (4, 57.4) -> (0.5, 57.4)
  line L18 (7.5, 44.9274) -> (7.5, 53.9)
  line L19 (10.5, 35.6) -> (10.5, 5.5)
  line L20 (5.5, 0.5) -> (0.5, 0.5)
  line L21 (-0.5, 57.4) -> (0.5, 57.4)
  line L22 (-0.5, 0.5) -> (0.5, 0.5)
  line L23 (2.5, 26.03) -> (-2.5, 26.03)
  line L24 (4, 31.33) -> (4, 27.53)
  line L25 (-2.5, 32.83) -> (2.5, 32.83)
  line L26 (-4, 27.53) -> (-4, 31.33)
  arc A1 centre (2, 35.6) radius 13 clockwise from (-11, 35.6) to (-8.5625, 43.1785)
  arc A2 centre (-4, 53.9) radius 4 clockwise from (-8, 53.9) to (-4, 57.9)
  arc A3 centre (-11, 44.9274) radius 3 clockwise from (-8, 44.9274) to (-8.5625, 43.1785)
  arc A4 centre (-2, 35.6) radius 13 clockwise from (8.5625, 43.1785) to (11, 35.6)
  arc A5 centre (11, 44.9274) radius 3 clockwise from (8.5625, 43.1785) to (8, 44.9274)
  arc A6 centre (4, 53.9) radius 4 clockwise from (4, 57.9) to (8, 53.9)
  arc A7 centre (-4, 53.9) radius 3.5 clockwise from (-7.5, 53.9) to (-4, 57.4)
  arc A8 centre (-11, 44.9274) radius 3.5 clockwise from (-7.5, 44.9274) to (-8.1562, 42.887)
  arc A9 centre (2, 35.6) radius 12.5 clockwise from (-10.5, 35.6) to (-8.1562, 42.887)
  arc A10 centre (4, 53.9) radius 3.5 clockwise from (4, 57.4) to (7.5, 53.9)
  arc A11 centre (11, 44.9274) radius 3.5 clockwise from (8.1563, 42.887) to (7.5, 44.9274)
  arc A12 centre (-2, 35.6) radius 12.5 clockwise from (8.1563, 42.887) to (10.5, 35.6)
  arc A13 centre (5.5, 5.5) radius 5 clockwise from (10.5, 5.5) to (5.5, 0.5)
  arc A14 centre (-5.5, 5.5) radius 5 clockwise from (-5.5, 0.5) to (-10.5, 5.5)
  arc A15 centre (2.5, 31.33) radius 1.5 clockwise from (2.5, 32.83) to (4, 31.33)
  arc A16 centre (-2.5, 31.33) radius 1.5 clockwise from (-4, 31.33) to (-2.5, 32.83)
  arc A17 centre (-2.5, 27.53) radius 1.5 clockwise from (-2.5, 26.03) to (-4, 27.53)
  arc A18 centre (2.5, 27.53) radius 1.5 clockwise from (4, 27.53) to (2.5, 26.03)
  point P54 (4, 32.83)
  point P52 (-4, 26.03)
  point P53 (4, 26.03)
  concentric A6 A10
  concentric A5 A11
  concentric A4 A12
  tangent L18 A11
  tangent L17 A10
  tangent A10 L18
  tangent A12 L19
  tangent A11 A12
  tangent L19 A13
  tangent L20 A13
  concentric A2 A7
  concentric A3 A8
  concentric A1 A9
  tangent L13 A8
  tangent L12 A7
  tangent A9 L14
  tangent A7 L13
  tangent A8 A9
  tangent L14 A14
  tangent L15 A14
  equal A13 A14
  horizontal L23
  vertical L24
  horizontal L25
  vertical L26
  coincident P54 L24
  coincident P54 L25
  tangent L24 A15
  tangent L25 A15
  tangent L25 A16
  tangent L26 A16
  equal A15 A16
  coincident P52 L23
  coincident P52 L26
  tangent L23 A17
  tangent L26 A17
  equal A15 A17
  coincident P53 L23
  coincident P53 L24
  tangent L23 A18
  tangent L24 A18
  equal A15 A18
  dimension "d862" radius A13 = 5
  dimension "d865" distance L20 L23 = 25.53
  dimension "d866" distance P52 P53 = 8
  dimension "d867" distance P53 P54 = 6.8
  dimension "d868" distance L5 P53 = 4 (= "d866 / 2")
  dimension "d869" radius A15 = 1.5
sketch "new profile" plane through (0, 0, 0) normal (0, 1, 0) x axis (1, 0, 0)
  line L1 (10.5537, 0.508) -> (-10.5537, 0.508)
  line L2 (0, 0.508) -> (0, 0)
  line L3 (10.5537, 31.4198) -> (10.5537, 0.508)
  line L4 (-8.4963, 31.4198) -> (8.4963, 31.4198)
  line L5 (0, 31.4198) -> (0, 0.508)
  line L6 (8.4963, 31.4198) -> (10.5537, 31.4198)
  line L7 (-10.5537, 31.4198) -> (-10.5537, 0.508)
  line L8 (-10.5537, 31.4198) -> (-8.4963, 31.4198)
  line L9 (8.4963, 40.3098) -> (8.4963, 31.4198)
  line L10 (8.9789, 40.3098) -> (-8.9789, 40.3098)
  line L11 (0, 40.3098) -> (0, 31.4198)
  line L12 (-8.4963, 40.3098) -> (-8.4963, 31.4198)
  line L13 (8.9789, 59.2836) -> (8.9789, 40.3098)
  line L14 (-8.9789, 59.2836) -> (-8.9789, 40.3098)
  line L15 (8.9789, 59.2836) -> (-8.9789, 59.2836)
  line L16 (5.08, 19.2024) -> (-5.08, 19.2024)
  line L17 (5.08, 13.4874) -> (5.08, 19.2024)
  line L18 (-5.08, 13.4874) -> (5.08, 13.4874)
  line L19 (-5.08, 19.2024) -> (-5.08, 13.4874)
  point P1 (0, 0)
  point P4 (0, 0)
  point P5 (0, 0.508)
  point P9 (0, 31.4198)
  point P10 (-10.5537, 31.4198)
  point P11 (-10.5537, 31.4198)
  point P15 (0, 40.3098)
  point P12 (8.4963, 40.3098)
  point P16 (-8.4963, 40.3098)
  point P2 (-10.5537, 0.508)
  point P3 (10.5537, 0.508)
  point P6 (10.5537, 31.4198)
  point P7 (8.4963, 31.4198)
  point P8 (-8.4963, 31.4198)
  point P13 (-8.9789, 40.3098)
  point P14 (8.9789, 40.3098)
  point P17 (8.9789, 59.2836)
  point P19 (-5.08, 19.2024)
  point P20 (5.08, 19.2024)
  point P22 (-5.08, 13.4874)
  horizontal L1
  coincident P1 P4
  midpoint L1 P5
  vertical L2
  perpendicular L1 L3
  perpendicular L3 L4
  midpoint L4 P9
  vertical L5
  perpendicular L4 L7
  parallel L4 L8
  collinear L4 L6
  coincident P10 P11
  perpendicular L4 L9
  horizontal L10
  midpoint L10 P15
  vertical L11
  coincident P12 L10
  coincident L10 P16
  perpendicular L10 L12
  perpendicular L10 L13
  perpendicular L10 L14
  perpendicular L13 L15
  horizontal L16
  vertical L17
  horizontal L18
  vertical L19
  dimension "d1178" distance P2 P3 = 21.1074
  dimension "d1179" distance P4 P5 = 0.508
  dimension "d1180" distance P3 P6 = 30.9118
  dimension "d1181" distance P7 P8 = 16.9926
  dimension "d1182" distance P7 P12 = 8.89
  dimension "d1183" distance P13 P14 = 17.9578
  dimension "d1184" distance P14 P17 = 18.9738
  dimension "d1185" distance L1 L16 = 18.6944
  dimension "d1186" distance P19 P20 = 10.16
  dimension "d1187" distance L5 L19 = 5.08 (= "d1186 / 2")
  dimension "d1188" distance P19 P22 = 5.715
extrude "Extrude1" new body sketch "new profile" profile of L1 L3 L4 L6 L7 L8 L9 L10 L12 L13 L14 L15 along normal blind 4
sketch "SpringRetention" plane through (0, 4, 0) normal (0, 1, 0) x axis (1, 0, 0)
  line L1 (5.1, 26.2) -> (-5.1, 26.2)
  line L2 (5.1, 23.2) -> (5.1, 26.2)
  line L3 (-5.1, 23.2) -> (5.1, 23.2)
  line L4 (-5.1, 26.2) -> (-5.1, 23.2)
  line L5 (1.5, 6.7) -> (-1.5, 6.7)
  line L6 (1.5, 42.8) -> (1.5, 6.7)
  line L7 (-1.5, 42.8) -> (1.5, 42.8)
  line L8 (-1.5, 6.7) -> (-1.5, 42.8)
  line L9 (5.5, 0.5) -> (0.5, 0.5)
  line L10 (0, 0.5) -> (0, 57.4)
  line L11 (8.1, 23.2) -> (8.1, 26.2)
  line L12 (-8.1, 26.2) -> (-8.1, 23.2)
  line L13 (2.5, 2.7) -> (-2.5, 2.7)
  line L14 (2.5, 43.8) -> (2.5, 2.7)
  line L15 (-2.5, 2.7) -> (-2.5, 43.8)
  line L16 (5.1, 26.2) -> (8.1, 26.2)
  line L17 (5.1, 23.2) -> (8.1, 23.2)
  line L18 (-5.1, 23.2) -> (-8.1, 23.2)
  line L19 (-5.1, 26.2) -> (-8.1, 26.2)
  line L20 (-2.5, 43.8) -> (2.5, 43.8)
  line L21 (-8.4963, 40.3098) -> (-8.9789, 40.3098)
  line L22 (-8.4963, 31.4198) -> (-8.4963, 40.3098)
  line L23 (-10.5537, 31.4198) -> (-8.4963, 31.4198)
  line L24 (-10.5537, 0.508) -> (-10.5537, 31.4198)
  line L25 (10.5537, 0.508) -> (-10.5537, 0.508)
  line L26 (10.5537, 31.4198) -> (10.5537, 0.508)
  line L27 (8.4963, 31.4198) -> (10.5537, 31.4198)
  line L28 (8.4963, 40.3098) -> (8.4963, 31.4198)
  line L29 (8.9789, 40.3098) -> (8.4963, 40.3098)
  line L30 (8.9789, 59.2836) -> (8.9789, 40.3098)
  line L31 (-8.9789, 59.2836) -> (8.9789, 59.2836)
  line L32 (-8.9789, 40.3098) -> (-8.9789, 59.2836)
  point P19 (2.5, 2.7)
  point P20 (2.5, 2.7)
  point P18 (-2.5, 2.7)
  point P23 (-2.5, 2.7)
  point P22 (-2.5, 43.8)
  point P25 (-2.5, 43.8)
  point P21 (2.5, 43.8)
  point P24 (2.5, 43.8)
  point P7 (1.5, 6.7)
  point P8 (1.5, 42.8)
  point P6 (-1.5, 6.7)
  point P3 (5.1, 26.2)
  point P4 (5.1, 23.2)
  point P5 (-5.1, 23.2)
  horizontal L1
  vertical L2
  horizontal L3
  vertical L4
  horizontal L5
  vertical L6
  horizontal L7
  vertical L8
  perpendicular L2 L16
  perpendicular L2 L17
  perpendicular L4 L18
  perpendicular L4 L19
  coincident P19 P20
  coincident P18 P23
  coincident P22 P25
  coincident P21 P24
  dimension "d870" distance P7 P8 = 36.1
  dimension "d871" distance P6 P7 = 3
  dimension "d872" distance P3 P4 = 3
  dimension "d873" distance P4 P5 = 10.2
  dimension "d875" distance L3 L5 = 16.5
  dimension "d876" distance L5 L9 = 6.2
  dimension "d877" distance L6 L10 = 1.5 (= "d872 / 2")
  dimension "d878" distance L2 L10 = 5.1 (= "d873 / 2")
  dimension "d881" distance L2 = -3
  dimension "d882" distance L4 = -3
  dimension "d883" = 4
  dimension "d884" = 1
  dimension "d885" = 1
  dimension "d886" = 1
derived_base_feature "Derived Base Feature1" bodies "true rear lock lug"
move "Move1"
move "Move2" TranslateX 0 TranslateY 0 TranslateZ 0.9
base_mesh_feature "Base Mesh Feature"
convert_mesh "Convert Mesh" bodies "MagpulFollower_223556", "MagpulFollower_223556 (1)", "MagpulFollower_223556 (2)", "MagpulFollower_223556 (3)", "MagpulFollower_223556 (4)"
